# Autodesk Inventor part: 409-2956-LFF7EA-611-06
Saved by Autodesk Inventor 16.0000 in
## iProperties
Created: 2010-06
Part Number: 409-2956-LFF7EA-611-06
Cost Center: 0 lbmass
Material: A36 STEEL PLATE
Document SubType Name: Sheet Metal
Designer: S. Boerckel
Authority: 0 in^3
Mass: 2082.98 g
Surface Area: 652.015 cm^2
Volume: 265.01 cm^3
Density: 7.86 g/cm^3
Flat Pattern Width: 43.815 cm
Flat Pattern Length: 6.35 cm
Flat Pattern Area: 278.225 cm^2
Sheet Metal Rule: 3/8"Thk
Sheet Metal Width: 4.4375 in
Sheet Metal Length: 71.0000 in^2
Description: PUMP MOUNT END GUSSET
User Status: BURN
SaveDate: 2008-01-15
SaveTime: 10:24
FileName: Sheet Metal
Wide: =<Flat Pattern Width>cm
Length: =<Flat Pattern Length>cm
Thickness: 0.3750 in
SMR: =<Sheet Metal Rule> - <Material>
Author: S. Boerckel
Revision Number: 0
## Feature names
1. Plate1
2. Cut1
